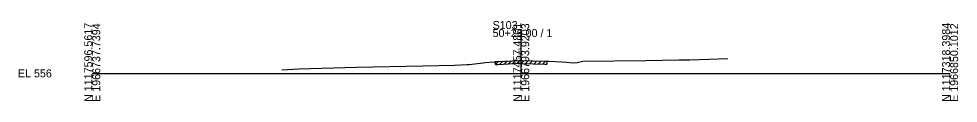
# Model space of a CAD drawing. Extents: x 974 to 1303, y 990 to 14518.
# Drawn here: x 974.3 to 1302.8, y 990.3 to 1018.3 of the extents above; entities that cross this region are included whole.
import ezdxf

# ---------------------------------------------------------------- set-up
doc = ezdxf.new("R2010")
doc.units = 0
for name, color, linetype in [('Level 10', 7, 'Continuous'), ('Level 60', 7, 'Continuous'), ('Level 61', 7, 'Continuous'), ('Level 63', 7, 'Continuous')]:
    doc.layers.add(name, color=color, linetype=linetype)

msp = doc.modelspace()

# ---------------------------------------------------------------- linework, layer by layer
at = {"layer": 'Level 60'}
for p, q in [((1072.28, 1001.54), (1092.37, 1002.19)), ((1092.37, 1002.19), (1115.61, 1002.65)), ((1115.61, 1002.65), (1126.65, 1002.87)), ((1126.65, 1002.87), (1131.14, 1003.07)), ((1131.14, 1003.07), (1131.86, 1003.11)), ((1131.86, 1003.11), (1136.69, 1003.7)), ((1136.69, 1003.7), (1137.26, 1003.76)), ((1137.26, 1003.76), (1140.62, 1004.06)), ((1140.62, 1004.06), (1141.02, 1004.09)), ((1141.02, 1004.09), (1141.79, 1004.13)), ((1141.79, 1004.13), (1149.28, 1004.52)), ((1149.28, 1004.52), (1150, 1004.5)), ((1150, 1004.5), (1158.29, 1004.25)), ((1158.29, 1004.25), (1159.02, 1004.23)), ((1159.02, 1004.23), (1159.65, 1004.21)), ((1159.65, 1004.21), (1164.25, 1004.05)), ((1164.25, 1004.05), (1165.87, 1003.93)), ((1165.87, 1003.93), (1168.02, 1003.63)), ((1168.02, 1003.63), (1169.61, 1003.82)), ((1169.61, 1003.82), (1171.59, 1004.22)), ((1171.59, 1004.22), (1193.59, 1004.55)), ((1193.59, 1004.55), (1205.26, 1004.73)), ((1205.26, 1004.73), (1208.93, 1004.78)), ((1208.93, 1004.78), (1222.22, 1005.16)), ((1066.31, 1001.28), (1072.28, 1001.54))]:
    msp.add_line(p, q, dxfattribs=at)
at = {"layer": 'Level 61'}
for p, q in [((1141.02, 1003.09), (1142.07, 1004.14)), ((1141.02, 1003.09), (1141.02, 1004.09)), ((1141.02, 1003.09), (1141.79, 1003.13)), ((1141.79, 1003.13), (1149.28, 1003.52)), ((1142.52, 1003.17), (1143.57, 1004.22)), ((1144.02, 1003.25), (1145.07, 1004.3)), ((1145.52, 1003.33), (1146.57, 1004.38)), ((1147.02, 1003.4), (1148.07, 1004.46)), ((1148.52, 1003.48), (1149.55, 1004.52)), ((1149.28, 1003.52), (1150, 1003.5)), ((1150, 1003.5), (1158.29, 1003.25)), ((1150.02, 1003.5), (1150.99, 1004.47)), ((1151.52, 1003.46), (1152.49, 1004.43)), ((1153.02, 1003.41), (1153.99, 1004.38)), ((1154.52, 1003.36), (1155.49, 1004.34)), ((1156.02, 1003.32), (1156.99, 1004.29)), ((1157.52, 1003.27), (1158.49, 1004.24)), ((1158.29, 1003.25), (1159.02, 1003.23)), ((1159.02, 1004.23), (1159.02, 1003.23)), ((1159.02, 1003.23), (1159.02, 1003.23))]:
    msp.add_line(p, q, dxfattribs=at)
at = {"layer": 'Level 63'}
for p, q in [((1150, 1000), (1150, 1015.49)), ((1000, 1000), (1150, 1000)), ((1150, 1000), (1300, 1000))]:
    msp.add_line(p, q, dxfattribs=at)

# ---------------------------------------------------------------- texts
at = {"layer": 'Level 10'}
msp.add_text('560.50', height=0.9, rotation=90, dxfattribs=at).set_placement((1149.95, 1005))
at = {"layer": 'Level 63'}
for s, p in [('N 1117596.5617', (1000, 990)), ('E 1966737.7394', (1002.8, 990)), ('N 1117457.4801', (1150, 990)), ('E 1966793.9203', (1152.8, 990)), ('N 1117318.3984', (1300, 990)), ('E 1966850.1012', (1302.8, 990))]:
    msp.add_text(s, height=2.8, rotation=90, dxfattribs=at).set_placement(p)
for s, p in [('50+25.00 / 1', (1140, 1012.69)), ('S103', (1140, 1015.49)), ('EL 556', (974, 998.6))]:
    msp.add_text(s, height=2.8, dxfattribs=at).set_placement(p)

doc.saveas('drawing.dxf')
